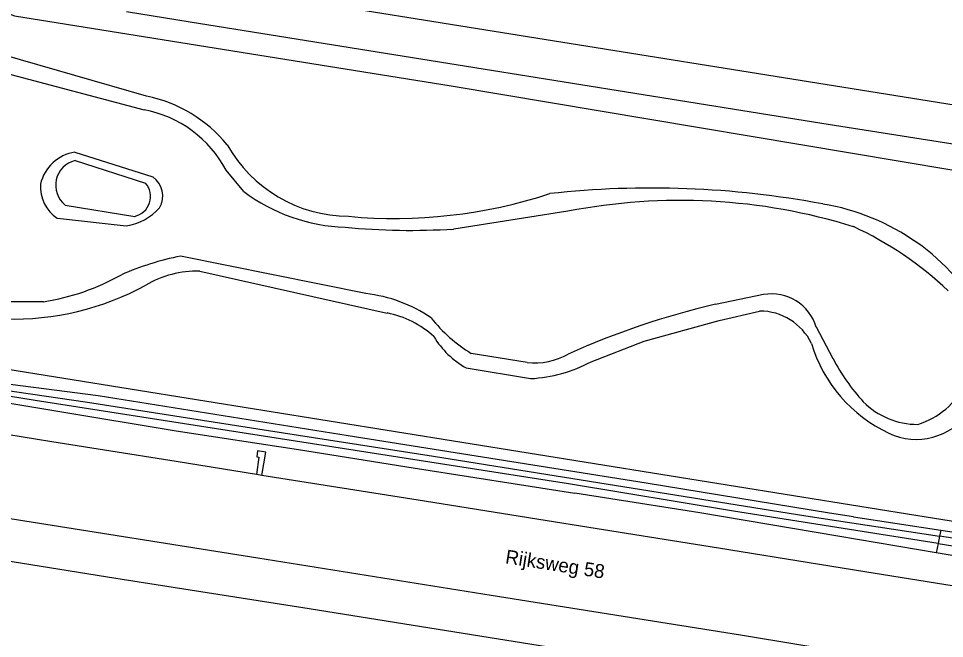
# Model space of a CAD drawing. Extents: x 131000 to 133013, y 393000 to 396501.
# Drawn here: x 131810.6 to 131977.5, y 394478 to 394589.8 of the extents above; entities that cross this region are included whole.
import ezdxf

# ---------------------------------------------------------------- set-up
doc = ezdxf.new("R2010")
doc.units = 0
for name, color, linetype in [('gg-afsc-hekwerk', 7, 'Continuous'), ('gg-anno-openbare ruimte label', 7, 'Continuous'), ('gg-bbg-hoofdgebouw', 7, 'Continuous'), ('gg-kntw-bovenkant insteek waterloop', 7, 'Continuous'), ('gg-kntw-waterlijn', 7, 'Continuous'), ('gt-grn-vlakafsluiter', 7, 'Continuous'), ('gx-grn-maaiveld', 7, 'Continuous')]:
    doc.layers.add(name, color=color, linetype=linetype)

msp = doc.modelspace()

# ---------------------------------------------------------------- linework, layer by layer
at = {"layer": 'gg-afsc-hekwerk'}
for p, q in [((131797.4, 394528.43), (131974.2, 394500)), ((131797.4, 394528.43), (131974.2, 394500)), ((131974.2, 394500), (132068.87, 394484.71)), ((131974.2, 394500), (132068.87, 394484.71))]:
    msp.add_line(p, q, dxfattribs=at)
at = {"layer": 'gg-bbg-hoofdgebouw'}
msp.add_lwpolyline([(131826.92, 394598.72), (132034.78, 394565.38), (132034.42, 394563.15), (132035.94, 394562.91), (132051.66, 394661.02), (131936.69, 394679.61)], dxfattribs=at)
at = {"layer": 'gg-kntw-bovenkant insteek waterloop'}
for p, q in [((131833.67, 394575.85), (131807.82, 394583.28)), ((131820.76, 394564.21), (131833.47, 394560.15)), ((131818.96, 394556.2), (131831.51, 394554.16)), ((131843.23, 394544.27), (131877.04, 394536.72)), ((131891.26, 394526.84), (131902.89, 394524.9)), ((131961.11, 394500), (131976.87, 394497.57)), ((131994.19, 394490.41), (131975.99, 394493.49))]:
    msp.add_line(p, q, dxfattribs=at)
for points in [[(131961.11, 394500), (131956.8, 394500.66), (131923.73, 394506.04), (131870, 394514.58), (131824.94, 394521.81), (131801.58, 394524.78), (131766, 394531.19), (131731.26, 394536.67)], [(131913.81, 394527.93), (131923.37, 394531.67), (131936.88, 394535.38), (131944.18, 394537.07)], [(131975.99, 394493.49), (131958.28, 394496.48), (131933.41, 394500.67), (131910.88, 394504.25)], [(131976.87, 394497.57), (131980.88, 394496.96), (132000, 394493.75)]]:
    msp.add_lwpolyline(points, dxfattribs=at)
for centre, radius, start, end in [((131828.3, 394550.61), 25.81, 39.5967, 77.9989), ((131870.25, 394579.48), 25.31, 209.3874, 269.5265), ((131821.84, 394559.76), 4.58, 103.7073, 231.0563), ((131830.71, 394557.73), 3.66, 282.6023, 41.2865), ((131878.35, 394643.71), 89.93, 264.6927, 288.1562), ((131924.68, 394392.62), 166.65, 79.3269, 96.3052), ((131948.82, 394515.78), 41.16, 29.0688, 80.5927), ((131842.73, 394526.3), 17.98, 88.4142, 120.8405), ((131809.53, 394585.91), 50.27, 268.4041, 298.496), ((131873.47, 394519.24), 17.85, 47.8642, 78.4726), ((131944.24, 394526.77), 10.3, 25.7431, 90.3344), ((131898.94, 394540.58), 15.74, 211.0159, 240.7971), ((131978.51, 394538.7), 26.08, 196.6267, 244.9387), ((131901.5, 394551.05), 26.19, 273.0423, 298.0259), ((131972.44, 394525.45), 11.51, 244.3733, 325.1971)]:
    msp.add_arc(centre, radius, start, end, dxfattribs=at)
at = {"layer": 'gg-kntw-waterlijn'}
for p, q in [((131807.39, 394580.23), (131833.21, 394573.35)), ((131820.73, 394565.75), (131834.78, 394561.29)), ((131851.17, 394558.62), (131848, 394562.46)), ((131909.6, 394555.07), (131889.02, 394551.87)), ((131817.57, 394553.81), (131829.99, 394552.44)), ((131873.19, 394540.22), (131839.79, 394547)), ((131944.89, 394540.05), (131936.25, 394538.29)), ((131957.42, 394528.49), (131954.4, 394534.15)), ((131902.29, 394527.79), (131892.19, 394529.45))]:
    msp.add_line(p, q, dxfattribs=at)
for points in [[(131597.45, 394558.73), (131597.35, 394558.2), (131598.28, 394557.22), (131614.81, 394554.32), (131658.22, 394547.05), (131706.84, 394539.2), (131725.21, 394536.23), (131756.59, 394531.16), (131784.73, 394526.62), (131802.4, 394523.65), (131822.99, 394520.62), (131855.64, 394515.54), (131885.41, 394510.91), (131952.48, 394500.17), (131976.63, 394496.49)], [(131976.35, 394495.15), (131971.79, 394495.88), (131939.49, 394500.99), (131909.73, 394505.94), (131813.58, 394520.94), (131648.04, 394547.8), (131595.78, 394556.58)], [(131815.08, 394538.75), (131807.88, 394538.75), (131777.78, 394545.72)]]:
    msp.add_lwpolyline(points, dxfattribs=at)
for centre, radius, start, end in [((131829.36, 394552.64), 21.07, 27.7795, 79.4677), ((131821.97, 394558.19), 7.66, 99.3534, 166.5551), ((131832.42, 394557.86), 4.16, 328.8874, 55.4759), ((131821.38, 394559.53), 6.88, 176.3393, 236.3437), ((131870.6, 394584.65), 32.48, 233.2539, 267.9749), ((131929.86, 394451.64), 105.39, 72.7645, 101.0833), ((131828.57, 394562.16), 9.82, 278.3351, 318.9997), ((131881.25, 394675.03), 123.4, 264.5123, 273.608), ((131934.12, 394494.07), 64.17, 46.6555, 65.1507), ((131849.95, 394496.19), 51.81, 101.3067, 113.708), ((131808.4, 394580.57), 42.35, 279.0767, 299.2902), ((131870.38, 394514.63), 25.74, 55.5126, 83.7333), ((131946.29, 394531.71), 8.46, 16.7799, 99.5589), ((131969.45, 394396.23), 145.9, 103.1532, 114.1906), ((131906.42, 394552.81), 27.35, 218.3187, 238.6508), ((131903.56, 394540.21), 12.49, 264.145, 299.224), ((131990.33, 394545.71), 37.14, 207.6133, 222.2896), ((131968.56, 394530.1), 14.08, 287.0347, 334.1833), ((131972.69, 394530.53), 13.89, 224.952, 269.9748)]:
    msp.add_arc(centre, radius, start, end, dxfattribs=at)
at = {"layer": 'gt-grn-vlakafsluiter'}
for p, q in [((131976.63, 394496.49), (131976.35, 394495.15)), ((131976.87, 394497.57), (131976.63, 394496.49)), ((131976.35, 394495.15), (131975.99, 394493.49))]:
    msp.add_line(p, q, dxfattribs=at)
at = {"layer": 'gx-grn-maaiveld'}
msp.add_line((131854.46, 394507.45), (131853.49, 394507.61), dxfattribs=at)
for points in [[(132053.96, 394627.45), (132045.54, 394575.05), (132042.86, 394559.35), (132042.13, 394558.35), (132040.98, 394557.63), (132038.88, 394557.72), (132017.51, 394561.13), (131955.42, 394570.9), (131841.5, 394589.17), (131830.06, 394591.05)], [(131804.57, 394608.97), (131804.57, 394597.72), (131804.84, 394595.05), (131805.34, 394593.58), (131806.22, 394592.29), (131807.72, 394591.11), (131809.85, 394590.32), (131819.19, 394588.82), (131888.59, 394577.68), (131987.42, 394561.09), (132039.2, 394552.4), (132041.26, 394552.34), (132043.54, 394552.81), (132045.7, 394553.75), (132047.32, 394555.03), (132048.39, 394556.31), (132049.53, 394558.22), (132050.34, 394560.63), (132051.75, 394570.01), (132059.11, 394616.14), (132059.53, 394618.56)], [(131653.08, 394545.64), (131674.02, 394541.91), (131695.46, 394538.53), (131716.97, 394535.4), (131740.53, 394531.42), (131766.76, 394527.11), (131795.91, 394522.62), (131838.99, 394515.47), (131861.04, 394512.1), (131881.73, 394508.79), (131910.88, 394504.25)], [(131853.49, 394507.61), (131839.01, 394509.93), (131816.55, 394513.49), (131789.93, 394517.81), (131763.69, 394522), (131736.93, 394526.25), (131710.11, 394530.55)], [(132033.96, 394463.49), (132020.91, 394465.6), (131983.52, 394471.55), (131940.74, 394478.61), (131895.79, 394485.81), (131853.7, 394492.51), (131809.04, 394499.63), (131765.33, 394506.63), (131726.06, 394512.85), (131682.77, 394519.67), (131648.53, 394525.24)], [(132033.38, 394458.46), (132029.51, 394459), (132002.6, 394462.54), (131976.36, 394466.1), (131941.58, 394471.15), (131906.12, 394476.45), (131862.98, 394483.36), (131828.14, 394488.86), (131800.75, 394493.22), (131774.67, 394497.34), (131757.41, 394500.15), (131739.27, 394502.97), (131716.81, 394506.48), (131679.84, 394512.41), (131652.07, 394516.93), (131646.66, 394517.79)], [(131854.46, 394507.45), (131855.18, 394511.66), (131853.65, 394511.86), (131853.51, 394510.79), (131853.9, 394510.73), (131853.49, 394507.61)], [(132036.67, 394478.36), (132026.47, 394479.95), (131990.46, 394485.67), (131963.13, 394490.05), (131936.76, 394494.3), (131911.87, 394498.3), (131883.79, 394502.78), (131854.46, 394507.45)], [(132393.51, 394448.27), (132393.24, 394448.21), (132391.77, 394448.26), (132388.81, 394448.54), (132378.36, 394449.82), (132370.18, 394450.17), (132341.3, 394453.29), (132297.88, 394457.11), (132263.93, 394460.34), (132238.47, 394462.99), (132214.65, 394465.32), (132175.47, 394469.61), (132158.14, 394471.88), (132141.87, 394473.43), (132072.18, 394481.18), (132057.95, 394483.2), (132005.32, 394491.53), (131982.61, 394495.58), (131976.63, 394496.49)], [(131976.35, 394495.15), (132050.16, 394483.39), (132072.09, 394479.98), (132088.56, 394478), (132177.69, 394468.26), (132211.95, 394464.45), (132269.05, 394458.9), (132323.32, 394453.95), (132340.29, 394452.47), (132365.93, 394449.82), (132377.92, 394448.15), (132384.13, 394447.41), (132389.62, 394446.78), (132393.17, 394446.43)]]:
    msp.add_lwpolyline(points, dxfattribs=at)

# ---------------------------------------------------------------- texts
at = {"layer": 'gg-anno-openbare ruimte label'}
msp.add_text('Rijksweg 58', height=2.5, rotation=351.1, dxfattribs=at).set_placement((131898.22, 394491.61))

doc.saveas('drawing.dxf')
